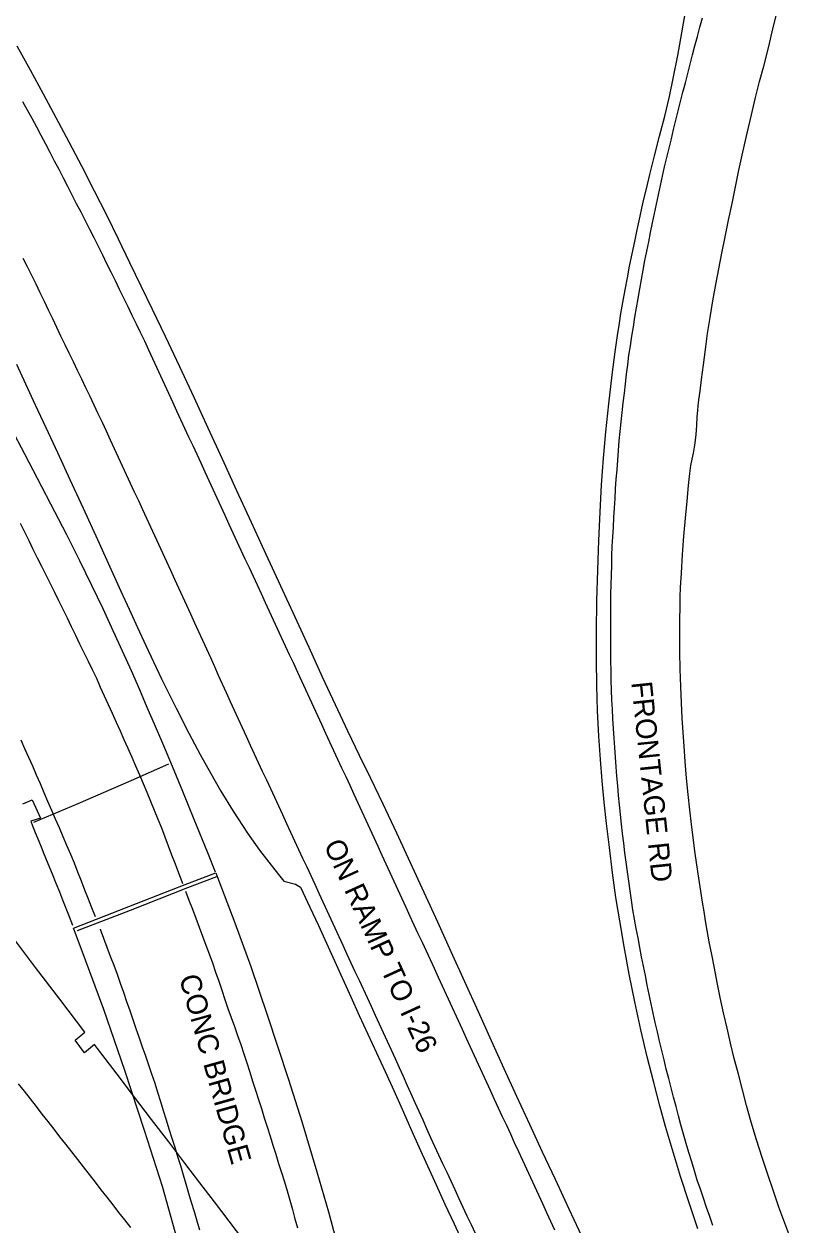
# Model space of a CAD drawing. Extents: x 1948091 to 1975253, y 787267 to 823306.
# Drawn here: x 1969109.2 to 1969309.1, y 798730.7 to 799043.5 of the extents above; entities that cross this region are included whole.
import ezdxf

# ---------------------------------------------------------------- set-up
doc = ezdxf.new("R2010")
doc.units = 0
for name, color, linetype in [('RD_EX_Bridge', 7, 'Continuous'), ('RD_EX_Bridge_Seam', 7, 'Continuous'), ('RD_EX_Conc', 7, 'Continuous'), ('RD_EX_Pavement_Markings', 7, 'Continuous'), ('RD_EX_Road', 7, 'Continuous'), ('RD_TX_RoadID', 7, 'Continuous')]:
    doc.layers.add(name, color=color, linetype=linetype)

msp = doc.modelspace()

# ---------------------------------------------------------------- linework, layer by layer
at = {"layer": 'RD_EX_Bridge'}
msp.add_lwpolyline([(1969150.3, 798723.06), (1969145.28, 798740.7), (1969140.64, 798755.34), (1969135.52, 798770.93), (1969129.99, 798786.84), (1969124.16, 798802.69), (1969122.13, 798808.06), (1969128.13, 798810.4), (1969140.54, 798815.23), (1969151.18, 798819.36), (1969159.18, 798822.45), (1969160.02, 798820.34), (1969164.19, 798809.38), (1969168.29, 798798.01), (1969172.59, 798785.47), (1969178.16, 798768.56), (1969181.6, 798757.62), (1969185.54, 798744.53), (1969188.53, 798734.16), (1969191.82, 798722.17)], dxfattribs=at)
at = {"layer": 'RD_EX_Bridge_Seam'}
msp.add_lwpolyline([(1969123.19, 798807.4), (1969137.01, 798812.72), (1969151.92, 798818.62), (1969159.44, 798821.47)], dxfattribs=at)
at = {"layer": 'RD_EX_Conc'}
msp.add_lwpolyline([(1969111.75, 798835.6), (1969123.33, 798840.52), (1969137.15, 798846.5), (1969146.93, 798850.78)], dxfattribs=at)
at = {"layer": 'RD_EX_Pavement_Markings'}
for points in [[(1969288.71, 798730.56), (1969287.9, 798732.93), (1969287.09, 798735.29), (1969286.28, 798737.65), (1969285.47, 798740.02), (1969284.66, 798742.38), (1969283.93, 798744.77), (1969283.21, 798747.17), (1969282.5, 798749.56), (1969281.78, 798751.95), (1969281.06, 798754.35), (1969280.42, 798756.76), (1969279.77, 798759.18), (1969279.13, 798761.59), (1969278.49, 798764.01), (1969277.85, 798766.43), (1969277.21, 798768.84), (1969276.57, 798771.26), (1969276, 798773.69), (1969275.42, 798776.12), (1969274.85, 798778.55), (1969274.28, 798780.99), (1969273.71, 798783.42), (1969273.14, 798785.85), (1969272.61, 798788.29), (1969272.12, 798790.75), (1969271.63, 798793.2), (1969271.15, 798795.65), (1969270.66, 798798.1), (1969270.17, 798800.55), (1969269.69, 798803), (1969269.23, 798805.46), (1969268.77, 798807.91), (1969268.31, 798810.37), (1969267.87, 798812.83), (1969267.52, 798815.3), (1969267.17, 798817.78), (1969266.81, 798820.25), (1969266.47, 798822.73), (1969266.14, 798825.2), (1969265.82, 798827.68), (1969265.49, 798830.16), (1969265.17, 798832.64), (1969264.92, 798835.13), (1969264.66, 798837.61), (1969264.41, 798840.1), (1969264.15, 798842.58), (1969263.93, 798845.07), (1969263.74, 798847.57), (1969263.55, 798850.06), (1969263.36, 798852.55), (1969263.17, 798855.04), (1969263, 798857.53), (1969262.85, 798860.03), (1969262.7, 798862.52), (1969262.55, 798865.02), (1969262.4, 798867.51), (1969262.31, 798870.01), (1969262.26, 798872.51), (1969262.21, 798875.01), (1969262.16, 798877.5), (1969262.11, 798880), (1969262.1, 798882.5), (1969262.1, 798885), (1969262.11, 798887.5), (1969262.11, 798890), (1969262.11, 798892.5), (1969262.14, 798895), (1969262.22, 798897.5), (1969262.29, 798899.99), (1969262.37, 798902.49), (1969262.44, 798904.99), (1969262.52, 798907.49), (1969262.65, 798909.98), (1969262.79, 798912.48), (1969262.94, 798914.97), (1969263.08, 798917.47), (1969263.23, 798919.96), (1969263.37, 798922.46), (1969263.57, 798924.95), (1969263.76, 798927.44), (1969263.95, 798929.93), (1969264.14, 798932.42), (1969264.34, 798934.91), (1969264.53, 798937.4), (1969264.81, 798939.89), (1969265.1, 798942.37), (1969265.38, 798944.85), (1969265.67, 798947.33), (1969265.96, 798949.82), (1969266.25, 798952.3), (1969266.54, 798954.78), (1969266.87, 798957.26), (1969267.25, 798959.73), (1969267.63, 798962.2), (1969268.01, 798964.67), (1969268.39, 798967.14), (1969268.81, 798969.6), (1969269.25, 798972.06), (1969269.68, 798974.52), (1969270.12, 798976.98), (1969270.55, 798979.44), (1969271.03, 798981.9), (1969271.52, 798984.35), (1969272, 798986.8), (1969272.49, 798989.25), (1969272.98, 798991.7), (1969273.49, 798994.15), (1969274.02, 798996.59), (1969274.54, 798999.03), (1969275.06, 799001.48), (1969275.58, 799003.92), (1969276.15, 799006.36), (1969276.74, 799008.78), (1969277.33, 799011.21), (1969277.91, 799013.64), (1969278.5, 799016.07), (1969279.1, 799018.5), (1969279.71, 799020.92), (1969280.33, 799023.34), (1969280.94, 799025.76), (1969281.55, 799028.19), (1969282.17, 799030.61), (1969282.79, 799033.03), (1969283.42, 799035.45), (1969284.06, 799037.86), (1969284.7, 799040.28), (1969285.34, 799042.7), (1969285.98, 799045.11)], [(1969108.87, 799023.34), (1969110.08, 799021.15), (1969111.28, 799018.96), (1969112.47, 799016.76), (1969113.63, 799014.55), (1969114.79, 799012.33), (1969115.96, 799010.12), (1969117.12, 799007.91), (1969118.28, 799005.69), (1969119.44, 799003.48), (1969120.6, 799001.26), (1969121.73, 798999.03), (1969122.86, 798996.81), (1969124, 798994.58), (1969125.13, 798992.35), (1969126.26, 798990.12), (1969127.39, 798987.89), (1969128.52, 798985.66), (1969129.65, 798983.43), (1969130.75, 798981.18), (1969131.85, 798978.94), (1969132.94, 798976.69), (1969134.04, 798974.45), (1969135.14, 798972.2), (1969136.24, 798969.95), (1969137.34, 798967.71), (1969138.44, 798965.46), (1969139.54, 798963.22), (1969140.6, 798960.96), (1969141.65, 798958.69), (1969142.7, 798956.42), (1969143.74, 798954.15), (1969144.79, 798951.88), (1969145.84, 798949.61), (1969146.89, 798947.34), (1969147.94, 798945.07), (1969148.98, 798942.8), (1969150.03, 798940.53), (1969151.08, 798938.26), (1969152.13, 798935.99), (1969153.18, 798933.72), (1969154.22, 798931.45), (1969155.27, 798929.18), (1969156.32, 798926.91), (1969157.37, 798924.64), (1969158.42, 798922.37), (1969159.46, 798920.1), (1969160.51, 798917.83), (1969161.56, 798915.56), (1969162.61, 798913.29), (1969163.66, 798911.03), (1969164.71, 798908.76), (1969165.76, 798906.49), (1969166.81, 798904.22), (1969167.86, 798901.95), (1969168.91, 798899.68), (1969169.96, 798897.41), (1969171.01, 798895.15), (1969172.06, 798892.88), (1969173.11, 798890.61), (1969174.16, 798888.34), (1969175.21, 798886.07), (1969176.26, 798883.8), (1969177.31, 798881.53), (1969178.36, 798879.27), (1969179.41, 798877), (1969180.46, 798874.73), (1969181.51, 798872.46), (1969182.56, 798870.19), (1969183.61, 798867.92), (1969184.66, 798865.65), (1969185.71, 798863.39), (1969186.76, 798861.12), (1969187.81, 798858.85), (1969188.86, 798856.58), (1969189.91, 798854.31), (1969190.95, 798852.04), (1969192, 798849.77), (1969193.05, 798847.5), (1969194.09, 798845.23), (1969195.14, 798842.96), (1969196.19, 798840.69), (1969197.23, 798838.42), (1969198.28, 798836.15), (1969199.33, 798833.88), (1969200.37, 798831.61), (1969201.42, 798829.34), (1969202.47, 798827.07), (1969203.51, 798824.8), (1969204.56, 798822.53), (1969205.61, 798820.26), (1969206.65, 798817.99), (1969207.7, 798815.72), (1969208.75, 798813.45), (1969209.8, 798811.18), (1969210.84, 798808.91), (1969211.89, 798806.64), (1969212.94, 798804.37), (1969213.98, 798802.1), (1969215.03, 798799.83), (1969216.08, 798797.56), (1969217.12, 798795.29), (1969218.17, 798793.02), (1969219.21, 798790.75), (1969220.26, 798788.48), (1969221.31, 798786.21), (1969222.35, 798783.94), (1969223.4, 798781.67), (1969224.45, 798779.4), (1969225.49, 798777.13), (1969226.54, 798774.86), (1969227.59, 798772.59), (1969228.63, 798770.32), (1969229.68, 798768.05), (1969230.73, 798765.78), (1969231.77, 798763.51), (1969232.82, 798761.24), (1969233.86, 798758.97), (1969234.91, 798756.7), (1969235.95, 798754.43), (1969236.99, 798752.15), (1969238.04, 798749.88), (1969239.08, 798747.61), (1969240.13, 798745.34), (1969241.17, 798743.07), (1969242.22, 798740.8), (1969243.26, 798738.53), (1969244.31, 798736.26), (1969245.36, 798733.99), (1969246.4, 798731.72), (1969247.45, 798729.45)], [(1969226.87, 798728.51), (1969225.79, 798730.77), (1969224.7, 798733.02), (1969223.64, 798735.28), (1969222.59, 798737.55), (1969221.54, 798739.82), (1969220.5, 798742.09), (1969219.45, 798744.36), (1969218.4, 798746.63), (1969217.35, 798748.9), (1969216.31, 798751.17), (1969215.26, 798753.44), (1969214.23, 798755.72), (1969213.21, 798758), (1969212.18, 798760.28), (1969211.16, 798762.56), (1969210.14, 798764.84), (1969209.11, 798767.12), (1969208.09, 798769.4), (1969207.06, 798771.68), (1969206.03, 798773.96), (1969204.98, 798776.23), (1969203.93, 798778.5), (1969202.89, 798780.77), (1969201.84, 798783.04), (1969200.79, 798785.31), (1969199.75, 798787.58), (1969198.7, 798789.85), (1969197.65, 798792.12), (1969196.61, 798794.39), (1969195.56, 798796.66), (1969194.51, 798798.93), (1969193.47, 798801.2), (1969192.42, 798803.47), (1969191.38, 798805.74), (1969190.33, 798808.01), (1969189.28, 798810.28), (1969188.23, 798812.55), (1969187.18, 798814.82), (1969186.12, 798817.09), (1969185.07, 798819.36), (1969184.02, 798821.62), (1969182.97, 798823.89), (1969181.92, 798826.16), (1969180.87, 798828.43), (1969179.82, 798830.7), (1969178.77, 798832.96), (1969177.71, 798835.23), (1969176.66, 798837.5), (1969175.61, 798839.77), (1969174.56, 798842.04), (1969173.51, 798844.3), (1969172.46, 798846.57), (1969171.4, 798848.84), (1969170.35, 798851.11), (1969169.3, 798853.37), (1969168.25, 798855.64), (1969167.2, 798857.91), (1969166.16, 798860.18), (1969165.12, 798862.46), (1969164.09, 798864.74), (1969163.05, 798867.01), (1969162.02, 798869.29), (1969160.98, 798871.56), (1969159.95, 798873.84), (1969158.91, 798876.11), (1969157.88, 798878.39), (1969156.84, 798880.66), (1969155.81, 798882.94), (1969154.77, 798885.22), (1969153.74, 798887.49), (1969152.7, 798889.77), (1969151.67, 798892.04), (1969150.63, 798894.32), (1969149.6, 798896.59), (1969148.56, 798898.87), (1969147.52, 798901.14), (1969146.47, 798903.41), (1969145.42, 798905.68), (1969144.37, 798907.95), (1969143.32, 798910.22), (1969142.26, 798912.48), (1969141.21, 798914.75), (1969140.16, 798917.02), (1969139.11, 798919.29), (1969138.06, 798921.55), (1969137, 798923.82), (1969135.95, 798926.09), (1969134.9, 798928.36), (1969133.85, 798930.63), (1969132.8, 798932.89), (1969131.74, 798935.16), (1969130.69, 798937.43), (1969129.64, 798939.7), (1969128.59, 798941.96), (1969127.52, 798944.22), (1969126.44, 798946.48), (1969125.36, 798948.73), (1969124.27, 798950.99), (1969123.19, 798953.24), (1969122.11, 798955.49), (1969121.03, 798957.75), (1969119.95, 798960), (1969118.86, 798962.25), (1969117.78, 798964.51), (1969116.7, 798966.76), (1969115.62, 798969.02), (1969114.54, 798971.27), (1969113.45, 798973.52), (1969112.37, 798975.78), (1969111.29, 798978.03), (1969110.16, 798980.26), (1969109.02, 798982.48)], [(1969108.23, 798913.47), (1969109.34, 798911.23), (1969110.46, 798908.99), (1969111.57, 798906.76), (1969112.69, 798904.52), (1969113.8, 798902.28), (1969114.92, 798900.05), (1969116.03, 798897.81), (1969117.15, 798895.57), (1969118.25, 798893.33), (1969119.35, 798891.08), (1969120.44, 798888.83), (1969121.53, 798886.59), (1969122.63, 798884.34), (1969123.72, 798882.09), (1969124.81, 798879.84), (1969125.91, 798877.6), (1969127, 798875.35), (1969128.08, 798873.1), (1969129.11, 798870.82), (1969130.14, 798868.54), (1969131.17, 798866.26), (1969132.19, 798863.98), (1969133.22, 798861.7), (1969134.25, 798859.42), (1969135.28, 798857.15), (1969136.3, 798854.87), (1969137.32, 798852.58), (1969138.31, 798850.29), (1969139.3, 798847.99), (1969140.28, 798845.69), (1969141.27, 798843.4), (1969142.21, 798841.08), (1969143.15, 798838.77), (1969144.09, 798836.45), (1969145.03, 798834.14), (1969145.94, 798831.81), (1969146.82, 798829.47), (1969147.7, 798827.13), (1969148.58, 798824.79), (1969149.47, 798822.46), (1969150.38, 798820.13), (1969150.56, 798819.66)], [(1969127.82, 798810.95), (1969126.92, 798813.28), (1969126.01, 798815.61), (1969125.11, 798817.94), (1969124.2, 798820.26), (1969123.29, 798822.59), (1969122.39, 798824.92), (1969121.4, 798827.22), (1969120.42, 798829.52), (1969119.43, 798831.81), (1969118.45, 798834.11), (1969117.46, 798836.41), (1969116.47, 798838.7), (1969115.48, 798841), (1969114.49, 798843.29), (1969113.5, 798845.59), (1969112.51, 798847.88), (1969111.53, 798850.18), (1969110.51, 798852.46), (1969109.48, 798854.74), (1969108.45, 798857.02)], [(1969151.33, 798817.67), (1969152.22, 798815.34), (1969153.1, 798812.99), (1969153.97, 798810.65), (1969154.84, 798808.31), (1969155.72, 798805.97), (1969156.6, 798803.63), (1969157.49, 798801.29), (1969158.35, 798798.95), (1969159.15, 798796.58), (1969159.96, 798794.21), (1969160.76, 798791.84), (1969161.56, 798789.47), (1969162.37, 798787.11), (1969163.21, 798784.76), (1969164.05, 798782.4), (1969164.89, 798780.05), (1969165.73, 798777.69), (1969166.5, 798775.31), (1969167.27, 798772.94), (1969168.03, 798770.55), (1969168.79, 798768.17), (1969169.55, 798765.79), (1969170.31, 798763.41), (1969171.07, 798761.03), (1969171.83, 798758.65), (1969172.58, 798756.26), (1969173.33, 798753.88), (1969174.08, 798751.49), (1969174.83, 798749.11), (1969175.58, 798746.72), (1969176.33, 798744.34), (1969177.08, 798741.95), (1969177.79, 798739.56), (1969178.48, 798737.15), (1969179.16, 798734.75), (1969179.84, 798732.34), (1969180.52, 798729.94)], [(1969155.04, 798729.33), (1969154.33, 798731.72), (1969153.62, 798734.12), (1969152.91, 798736.52), (1969152.2, 798738.92), (1969151.5, 798741.31), (1969150.79, 798743.71), (1969150.06, 798746.1), (1969149.32, 798748.49), (1969148.58, 798750.88), (1969147.83, 798753.26), (1969147.09, 798755.65), (1969146.35, 798758.04), (1969145.61, 798760.43), (1969144.87, 798762.81), (1969144.13, 798765.2), (1969143.38, 798767.59), (1969142.57, 798769.95), (1969141.75, 798772.31), (1969140.94, 798774.68), (1969140.12, 798777.04), (1969139.31, 798779.4), (1969138.49, 798781.77), (1969137.67, 798784.13), (1969136.86, 798786.49), (1969136.04, 798788.85), (1969135.23, 798791.22), (1969134.41, 798793.58), (1969133.57, 798795.93), (1969132.69, 798798.27), (1969131.81, 798800.61), (1969130.93, 798802.95), (1969130.05, 798805.29), (1969129.17, 798807.63), (1969129.12, 798807.77)], [(1969107.73, 798767.48), (1969109.28, 798765.52), (1969110.82, 798763.55), (1969112.36, 798761.58), (1969113.9, 798759.61), (1969115.44, 798757.64), (1969116.97, 798755.67), (1969118.51, 798753.7), (1969120.05, 798751.73), (1969121.59, 798749.76), (1969123.13, 798747.79), (1969124.66, 798745.82), (1969126.2, 798743.85), (1969127.74, 798741.88), (1969129.28, 798739.9), (1969130.82, 798737.93), (1969132.35, 798735.96), (1969133.89, 798733.99), (1969135.43, 798732.02), (1969136.97, 798730.05)]]:
    msp.add_lwpolyline(points, dxfattribs=at)
at = {"layer": 'RD_EX_Road'}
for points in [[(1969284.83, 798729.72), (1969282.53, 798736.47), (1969280.31, 798743.35), (1969278.21, 798750.24), (1969276.41, 798756.36), (1969274.9, 798761.78), (1969273.33, 798767.79), (1969271.64, 798774.53), (1969269.97, 798781.57), (1969268.36, 798788.79), (1969266.89, 798796.05), (1969265.57, 798803.26), (1969264.44, 798809.89), (1969263.48, 798816), (1969262.58, 798822.39), (1969261.75, 798829.07), (1969261.03, 798835.24), (1969260.42, 798840.86), (1969259.91, 798846.39), (1969259.46, 798851.99), (1969259.05, 798858.07), (1969258.68, 798864.63), (1969258.46, 798871.23), (1969258.38, 798877.91), (1969258.4, 798885.28), (1969258.52, 798893.32), (1969258.72, 798901.26), (1969259.01, 798908.96), (1969259.34, 798916.37), (1969259.73, 798923.49), (1969260.21, 798930.43), (1969260.82, 798937.31), (1969261.59, 798944.62), (1969262.48, 798952.14), (1969263.26, 798958.12), (1969263.88, 798962.39), (1969264.37, 798965.62), (1969264.77, 798968.11), (1969265.25, 798970.96), (1969265.84, 798974.27), (1969266.44, 798977.45), (1969267.02, 798980.47), (1969267.67, 798983.65), (1969268.35, 798986.91), (1969268.9, 798989.52), (1969269.31, 798991.49), (1969269.75, 798993.47), (1969270.23, 798995.59), (1969270.77, 798997.91), (1969271.4, 799000.58), (1969272.33, 799004.36), (1969273.55, 799009.22), (1969274.86, 799014.33), (1969276.2, 799019.5), (1969277.41, 799024.63), (1969278.49, 799029.77), (1969279.56, 799035.32), (1969280.63, 799041.23), (1969281.58, 799046.69)], [(1969309.08, 798727.05), (1969307.46, 798731.22), (1969305.94, 798735.39), (1969304.53, 798739.55), (1969303.06, 798743.85), (1969301.53, 798748.31), (1969300.06, 798752.89), (1969298.66, 798757.51), (1969297.45, 798761.85), (1969296.41, 798765.9), (1969295.37, 798769.96), (1969294.31, 798774.06), (1969293.33, 798778.08), (1969292.44, 798782), (1969291.53, 798785.96), (1969290.62, 798789.96), (1969289.82, 798793.83), (1969289.11, 798797.56), (1969288.43, 798801.12), (1969287.77, 798804.48), (1969287.24, 798807.43), (1969286.83, 798809.96), (1969286.43, 798812.39), (1969286.01, 798814.82), (1969285.55, 798817.69), (1969285.05, 798821.01), (1969284.54, 798824.51), (1969284.03, 798828.11), (1969283.57, 798831.61), (1969283.16, 798835.06), (1969282.73, 798838.8), (1969282.28, 798842.85), (1969281.88, 798847.11), (1969281.54, 798851.46), (1969281.23, 798855.4), (1969280.97, 798858.94), (1969280.74, 798862.68), (1969280.52, 798866.73), (1969280.34, 798870.99), (1969280.19, 798875.45), (1969280.11, 798880), (1969280.09, 798884.53), (1969280.12, 798888.42), (1969280.17, 798891.59), (1969280.24, 798894.29), (1969280.33, 798896.79), (1969280.53, 798900.46), (1969280.84, 798905.33), (1969281.2, 798910.16), (1969281.61, 798914.78), (1969282.01, 798919.2), (1969282.4, 798923.32), (1969282.73, 798926.42), (1969283.01, 798928.5), (1969283.31, 798930.19), (1969283.65, 798931.73), (1969284, 798933.84), (1969284.34, 798936.51), (1969284.56, 798939.03), (1969284.67, 798941.22), (1969284.77, 798942.85), (1969284.9, 798944.04), (1969285.1, 798945.67), (1969285.4, 798947.91), (1969285.79, 798950.96), (1969286.27, 798954.77), (1969286.79, 798958.77), (1969287.35, 798962.89), (1969287.99, 798967.12), (1969288.7, 798971.43), (1969289.46, 798975.63), (1969290.24, 798979.72), (1969291.06, 798983.87), (1969291.91, 798988.1), (1969292.82, 798992.41), (1969293.76, 798996.77), (1969294.66, 799001.1), (1969295.53, 799005.44), (1969296.55, 799010.11), (1969297.69, 799015.1), (1969298.79, 799019.87), (1969299.83, 799024.34), (1969300.89, 799028.52), (1969302, 799032.56), (1969303.19, 799037.34), (1969304.41, 799042.62), (1969305.28, 799046)], [(1969107.33, 799037.84), (1969110.82, 799031.56), (1969114.22, 799025.36), (1969117.56, 799019.18), (1969120.92, 799012.85), (1969124.29, 799006.39), (1969127.55, 799000.04), (1969130.69, 798993.82), (1969133.74, 798987.6), (1969136.72, 798981.39), (1969139.66, 798975.32), (1969142.63, 798969.24), (1969145.99, 798962.24), (1969149.73, 798954.3), (1969153.47, 798946.29), (1969157.16, 798938.31), (1969160.88, 798930.23), (1969164.64, 798922.01), (1969168.43, 798913.74), (1969172.25, 798905.44), (1969176.03, 798897.22), (1969179.77, 798889.11), (1969183.41, 798881.2), (1969186.94, 798873.52), (1969190.33, 798866.24), (1969193.55, 798859.39), (1969196.59, 798853.08), (1969199.51, 798847.12), (1969202.74, 798840.39), (1969206.28, 798832.82), (1969209.87, 798825.11), (1969213.44, 798817.38), (1969216.96, 798809.67), (1969220.45, 798801.95), (1969223.97, 798794.16), (1969227.54, 798786.33), (1969230.98, 798778.77), (1969234.28, 798771.5), (1969237.59, 798764.24), (1969240.91, 798756.97), (1969244.23, 798749.78), (1969247.59, 798742.6), (1969251.19, 798734.92), (1969255.09, 798726.62)], [(1969107.29, 798954.91), (1969109.64, 798949.77), (1969112.13, 798944.35), (1969114.88, 798938.4), (1969117.93, 798931.89), (1969121.18, 798924.88), (1969124.63, 798917.38), (1969128.37, 798909.21), (1969132.39, 798900.39), (1969134.47, 798895.81), (1969136.61, 798891.13), (1969138.78, 798886.36), (1969140.95, 798881.66), (1969145.05, 798873), (1969148.84, 798865.35), (1969152.21, 798858.77), (1969155.15, 798853.23), (1969157.87, 798848.29), (1969160.49, 798843.72), (1969163.72, 798838.5), (1969167.47, 798832.77), (1969170.6, 798828.32), (1969173.04, 798825.19), (1969175.57, 798821.97), (1969176.91, 798820.24), (1969179.93, 798819.48), (1969181.28, 798818.67), (1969183.74, 798813.53), (1969185.94, 798808.75), (1969188.02, 798804.15), (1969190.1, 798799.55), (1969192.21, 798794.9), (1969194.39, 798790.12), (1969196.6, 798785.29), (1969198.83, 798780.43), (1969201.08, 798775.55), (1969203.34, 798770.65), (1969205.59, 798765.74), (1969207.78, 798760.84), (1969209.96, 798755.94), (1969212.14, 798751.03), (1969214.35, 798746.1), (1969216.61, 798741.16), (1969218.92, 798736.15), (1969221.3, 798731.02), (1969223.69, 798725.89)], [(1969159.12, 798822.6), (1969157.13, 798827.6), (1969153.61, 798836.35), (1969150.65, 798843.6), (1969147.92, 798850.14), (1969145.39, 798856.09), (1969143.21, 798861.16), (1969141.35, 798865.5), (1969139.38, 798870.08), (1969137.23, 798875.05), (1969134.93, 798880.19), (1969132.5, 798885.5), (1969129.82, 798891.21), (1969126.88, 798897.31), (1969123.75, 798903.68), (1969120.36, 798910.43), (1969116.26, 798918.45), (1969113.91, 798922.99), (1969109.46, 798931.52), (1969105.87, 798938.23)], [(1969108.95, 798840.43), (1969111.34, 798841.41), (1969113.56, 798836.71), (1969110.98, 798835.9), (1969111.45, 798834.68), (1969112.15, 798832.92), (1969113.08, 798830.64), (1969113.84, 798828.8), (1969114.24, 798827.82), (1969115.46, 798824.87), (1969116.57, 798822.16), (1969117.56, 798819.7), (1969118.44, 798817.49), (1969119.28, 798815.38), (1969120.13, 798813.22), (1969121, 798811.02), (1969121.88, 798808.77)], [(1969166.55, 798726.63), (1969162.7, 798731.69), (1969158.87, 798736.71), (1969155.06, 798741.7), (1969151.13, 798746.84), (1969146.93, 798752.34), (1969142.48, 798758.19), (1969137.76, 798764.38), (1969133.49, 798770), (1969130.38, 798774.09), (1969128.41, 798776.67), (1969127.6, 798777.73), (1969125.02, 798775.54), (1969122.56, 798778.83), (1969125.12, 798780.95), (1969118.55, 798789.52), (1969112.26, 798797.79), (1969106.24, 798805.74)]]:
    msp.add_lwpolyline(points, dxfattribs=at)

# ---------------------------------------------------------------- texts
at = {"layer": 'RD_TX_RoadID'}
for s, rotation, p in [('FRONTAGE RD', 275.9345, (1969267.45, 798872.03)), ('ON RAMP TO I-26', 294.5969, (1969187.24, 798829.71)), ('CONC BRIDGE', 285.6956, (1969149.59, 798795.18))]:
    msp.add_text(s, height=5.4, rotation=rotation, dxfattribs=at).set_placement(p)

doc.saveas('drawing.dxf')
